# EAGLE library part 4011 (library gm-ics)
Quad 2-input NAND
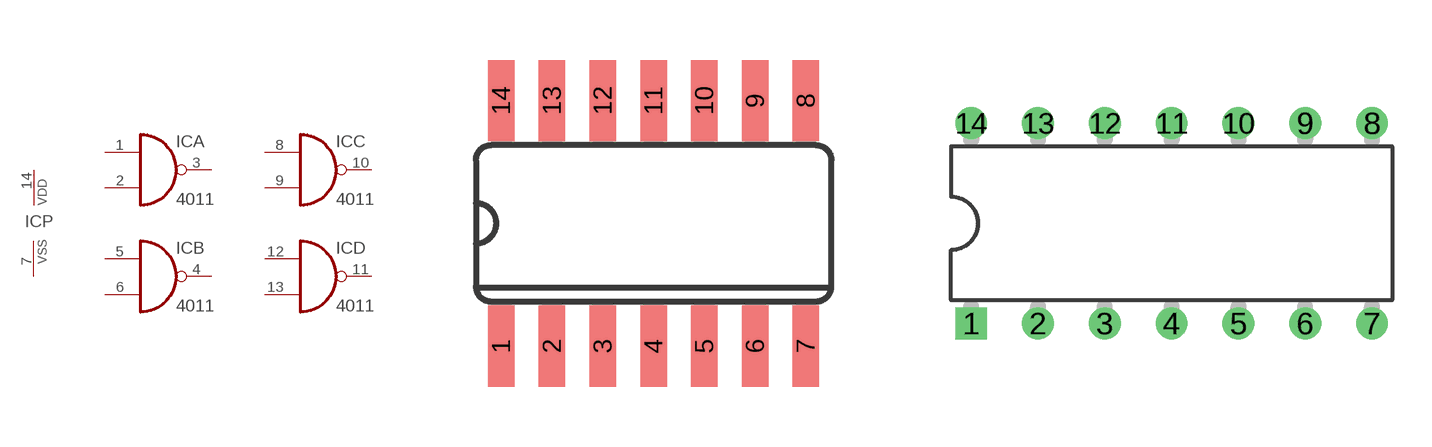
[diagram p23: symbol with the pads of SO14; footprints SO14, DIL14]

Designator prefix IC; gates A=4011 B=4011 C=4011 D=4011 P=PWRN

## 4011D  [SO14]
1  A:I0  in
2  A:I1  in
3  A:O  out
4  B:O  out
5  B:I0  in
6  B:I1  in
7  P:VSS  pwr
8  C:I0  in
9  C:I1  in
10  C:O  out
11  D:O  out
12  D:I0  in
13  D:I1  in
14  P:VDD  pwr

## 4011N  [DIL14]
Pads as for SO14

## Footprint SO14 (pad centres in mm)
Small Outline package 150 mil
smd 0.66 x 2.032: 1 -3.81,-3.073; 2 -2.54,-3.073; 3 -1.27,-3.073; 4 0,-3.073; 5 1.27,-3.073; 6 2.54,-3.073; 7 3.81,-3.073; 8 3.81,3.073; 9 2.54,3.073; 10 1.27,3.073; 11 0,3.073; 12 -1.27,3.073; 13 -2.54,3.073; 14 -3.81,3.073

## Footprint DIL14 (pad centres in mm)
Dual In Line Package
drill 0.7 square: 1 -7.62,-3.81
drill 0.7 round: 2 -5.08,-3.81; 3 -2.54,-3.81; 4 0,-3.81; 5 2.54,-3.81; 6 5.08,-3.81; 7 7.62,-3.81; 8 7.62,3.81; 9 5.08,3.81; 10 2.54,3.81; 11 0,3.81; 12 -2.54,3.81; 13 -5.08,3.81; 14 -7.62,3.81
